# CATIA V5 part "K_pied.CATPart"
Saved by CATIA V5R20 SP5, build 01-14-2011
Part number: pied
Bounding box of the stored display mesh (mm): x 0 to 50, y -55 to 55, z -225 to 225
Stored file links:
  G:\Khaled_CFAO_2011\ST2M\ST2M_GR1\lpierredon\Khaled\CAD_thinkMOTION\K_pied.CATPart
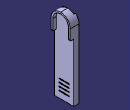
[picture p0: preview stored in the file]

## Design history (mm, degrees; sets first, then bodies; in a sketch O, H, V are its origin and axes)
Set1
  Plane1: type Offset, RefPlane yz-plane, Offset 30
Body1 (main body)
  Sketch1 on yz-plane, origin (0, 0, 0), H (0, 1, 0), V (0, 0, 1)
    line L1 (-55, 225) -> (55, 225)
    line L2 (55, 225) -> (55, -225)
    line L3 (55, -225) -> (-55, -225)
    line L4 (-55, -225) -> (-55, 225)
    length L2 = 450
    length L3 = 110
    horizontal: L1 H, L3 H
    vertical: L2 V, L4 V
    symmetry: L2 L4 V, L1 L3 H
  Pad1: profile Sketch1, direction (1, 0, 0), length 30
  Sketch2 on yz-plane, origin (0, 0, 0), H (0, 1, 0), V (0, 0, 1)
    line L1 (35, 225) -> (-35, 225)
    line L2 (-35, 225) -> (-35, -225)
    line L3 (-35, -225) -> (35, -225)
    line L4 (35, -225) -> (35, 225)
    length L2 = 450
    length L1 = 70
    horizontal: L1 H, L3 H
    vertical: L2 V, L4 V
    symmetry: L2 L4 V, L1 L3 H
  Pocket1: profile Sketch2, direction (1, 0, 0), length 10
  Sketch3 on Plane1, origin (30, 0, 0), H (0, 1, 0), V (0, 0, 1)
    arc A1 centre (0, 170.728) radius 45 from (-45, 170.728) to (45, 170.728) cw
    point P1 (0, 170.728)
    reference projected line E1 (55, -225) -> (55, 225) from edge [face of Pad1 from Sketch1.L2 | end face of Pad1]
    line L1 (-45, 170.728) -> (-45, 108)
    line L2 (-45, 108) -> (-55, 108)
    line L3 (45, 170.728) -> (45, 108)
    point P6 (45, 108)
    line L4 (45, 108) -> (55, 108)
    line L5 (-55, 108) -> (-55, 225)
    line L6 (-55, 225) -> (55, 225)
    line L7 (55, 225) -> (55, 108)
    reference projected line E2 (55, -225) -> (55, 225) from edge [face of Pad1 from Sketch1.L2 | end face of Pad1]
    reference projected line E3 (-55, 225) -> (-55, -225) from edge [face of Pad1 from Sketch1.L4 | end face of Pad1]
    reference projected line E4 (55, 225) -> (-55, 225) from edge [face of Pad1 from Sketch1.L1 | end face of Pad1]
    radius A1 = 45
    distance P1 E1 = 55
    vertical: L1 V, L3 V, L5 V, L7 V
    tangency: L1 A1, A1 L3
    horizontal: L2 H, L4 H, L6 H
    coincidence: P6 L2, L7 E2, L5 E3, L6 E4
  Pad2: profile Sketch3, direction (1, 0, 0), length 20
  Fillet1: radius 55, on edge [face of Pad2 | face of Pad2] (x2)
  Fillet2: radius 5, on edge [face of Pad2 from Sketch3.L4 | end face of Pad2]; edge [face of Pad2 from Sketch3.L2 | end face of Pad2]
  Sketch4 on Plane1, origin (30, 0, 0), H (0, 1, 0), V (0, 0, 1)
    line L1 (-30, -145) -> (30, -145)
    line L2 (30, -145) -> (30, -150)
    line L3 (30, -150) -> (-30, -150)
    line L4 (-30, -150) -> (-30, -145)
    point P5 (-30, -165)
    line L5 (-30, -165) -> (30, -165)
    line L6 (30, -165) -> (30, -170)
    line L7 (30, -170) -> (-30, -170)
    line L8 (-30, -170) -> (-30, -165)
    point P7 (30, -170)
    point P9 (-30, -185)
    line L9 (-30, -185) -> (30, -185)
    line L10 (30, -185) -> (30, -190)
    line L11 (30, -190) -> (-30, -190)
    line L12 (-30, -190) -> (-30, -185)
    point P11 (30, -190)
    point P13 (-30, -125)
    line L13 (-30, -125) -> (30, -125)
    line L14 (30, -125) -> (30, -130)
    line L15 (30, -130) -> (-30, -130)
    line L16 (-30, -130) -> (-30, -125)
    point P15 (30, -130)
    reference projected line E1 (-55, 225) -> (-55, -225) from edge [face of Pad2 | end face of Pad1]
    distance L15 L1 = 15
    length L14 = 5
    length L2 = 5
    length L6 = 5
    length L10 = 5
    distance L3 L5 = 15
    distance L9 L7 = 15
    distance L16 E1 = 25
    length L13 = 60
    horizontal: L1 H, L3 H, L5 H, L7 H, L9 H, L11 H, L13 H, L15 H
    vertical: L2 V, L4 V, L6 V, L8 V, L10 V, L12 V, L14 V, L16 V
    coincidence: P5 L4, P7 L2, P9 L4, P11 L2, P13 L4, P15 L2
  Pad3: profile Sketch4, direction (1, 0, 0), length 1
  Fillet3: radius 1, on edge [face of Pad3 from Sketch4.L14 | end face of Pad3]; edge [face of Pad3 from Sketch4.L2 | end face of Pad3]; edge [face of Pad3 from Sketch4.L6 | end face of Pad3]; edge [face of Pad3 from Sketch4.L10 | end face of Pad3]
  Fillet4: radius 1, on edge [face of Pad3 from Sketch4.L16 | end face of Pad3]; edge [face of Pad3 from Sketch4.L4 | end face of Pad3]; edge [face of Pad3 from Sketch4.L8 | end face of Pad3]; edge [face of Pad3 from Sketch4.L12 | end face of Pad3]
  Fillet5: radius 1, on edge [face of Pad3 from Sketch4.L15 | face of Fillet3]; edge [face of Pad3 from Sketch4.L3 | face of Fillet3]; edge [face of Pad3 from Sketch4.L7 | face of Fillet3]; edge [face of Pad3 from Sketch4.L11 | face of Fillet3]
  Fillet6: radius 1, on edge [face of Pad3 from Sketch4.L13 | face of Fillet3]; edge [face of Pad3 from Sketch4.L1 | face of Fillet3]; edge [face of Pad3 from Sketch4.L5 | face of Fillet3]; edge [face of Pad3 from Sketch4.L9 | face of Fillet3]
